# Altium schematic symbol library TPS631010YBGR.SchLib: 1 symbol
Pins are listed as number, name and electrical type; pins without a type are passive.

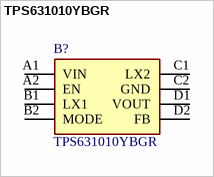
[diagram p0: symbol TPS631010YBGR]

## TPS631010YBGR
designator B?
Texas Instruments; Geometry.Height: 0.5mm
footprint BGA8C40P2X4_86X176X50
pins: A1 VIN, A2 EN, B1 LX1, B2 MODE, C1 LX2, C2 GND, D1 VOUT, D2 FB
